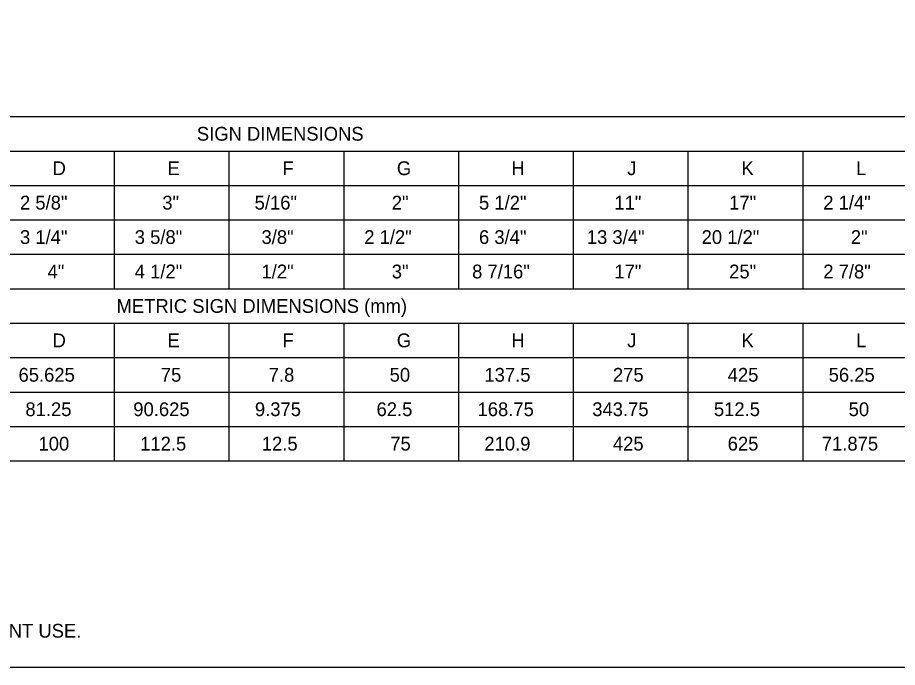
# Model space of a CAD drawing. Extents: x 49991.4 to 50021, y 49987.6 to 50011.4.
# Drawn here: x 50007.711 to 50011.545, y 49987.799 to 49990.63 of the extents above; entities that cross this region are included whole.
import ezdxf

# ---------------------------------------------------------------- set-up
doc = ezdxf.new("R2010")
doc.units = 0
doc.layers.add('Level 1', color=7, linetype='Continuous')
doc.layers.add('Level 2', color=7, linetype='Continuous')

msp = doc.modelspace()

# ---------------------------------------------------------------- linework, layer by layer
at = {"layer": 'Level 1'}
msp.add_lwpolyline([(49999.3835, 49998.9992), (50016.7501, 49998.9992), (50016.7501, 49987.7988), (49999.3835, 49987.7988)], close=True, dxfattribs=at)
at = {"layer": 'Level 2'}
for p, q in [((50005.0051, 49990.1985), (50013.6326, 49990.1985)), ((50006.1326, 49990.0485), (50013.6326, 49990.0485)), ((50008.1326, 49990.0485), (50008.1326, 49989.4485)), ((50008.6326, 49990.0485), (50008.6326, 49989.4485)), ((50009.1326, 49990.0485), (50009.1326, 49989.4485)), ((50009.6326, 49990.0485), (50009.6326, 49989.4485)), ((50010.1326, 49990.0485), (50010.1326, 49989.4485)), ((50010.6326, 49990.0485), (50010.6326, 49989.4485)), ((50011.1326, 49990.0485), (50011.1326, 49989.4485)), ((50005.0051, 49989.8985), (50013.6326, 49989.8985)), ((50005.0051, 49989.7485), (50013.6326, 49989.7485)), ((50005.0051, 49989.5985), (50013.6326, 49989.5985)), ((50005.0051, 49989.4485), (50013.6326, 49989.4485)), ((50005.0051, 49989.4485), (50013.6326, 49989.4485)), ((50006.1326, 49989.2985), (50013.6326, 49989.2985)), ((50008.1326, 49989.2985), (50008.1326, 49988.6985)), ((50008.6326, 49989.2985), (50008.6326, 49988.6985)), ((50009.1326, 49989.2985), (50009.1326, 49988.6985)), ((50009.6326, 49989.2985), (50009.6326, 49988.6985)), ((50010.1326, 49989.2985), (50010.1326, 49988.6985)), ((50010.6326, 49989.2985), (50010.6326, 49988.6985)), ((50011.1326, 49989.2985), (50011.1326, 49988.6985)), ((50005.0051, 49989.1485), (50013.6326, 49989.1485)), ((50005.0051, 49988.9985), (50013.6326, 49988.9985)), ((50005.0051, 49988.8485), (50013.6326, 49988.8485)), ((50005.0051, 49988.6985), (50013.6326, 49988.6985))]:
    msp.add_line(p, q, dxfattribs=at)

# ---------------------------------------------------------------- texts
for s, p in [('SIGN DIMENSIONS', (50008.4926, 49990.0935)), ('D', (50007.8639, 49989.9435)), ('E', (50008.3642, 49989.9435)), ('F', (50008.8654, 49989.9435)), ('G', (50009.3639, 49989.9435)), ('H', (50009.863, 49989.9435)), ('J', (50010.3677, 49989.9435)), ('K', (50010.8656, 49989.9435)), ('L', (50011.3656, 49989.9435)), ('2 5/8"', (50007.7219, 49989.7935)), ('3"', (50008.342, 49989.7935)), (' 5/16"', (50008.722, 49989.7935)), ('2"', (50009.342, 49989.7935)), ('5 1/2"', (50009.722, 49989.7935)), ('11"', (50010.3119, 49989.7935)), ('17"', (50010.812, 49989.7935)), ('2 1/4"', (50011.222, 49989.7935)), ('3 1/4"', (50007.7219, 49989.6435)), ('3 5/8"', (50008.222, 49989.6435)), (' 3/8"', (50008.752, 49989.6435)), ('2 1/2"', (50009.2219, 49989.6435)), ('6 3/4"', (50009.722, 49989.6435)), ('13 3/4"', (50010.1919, 49989.6435)), ('20 1/2"', (50010.692, 49989.6435)), ('2"', (50011.3421, 49989.6435)), ('4"', (50007.842, 49989.4935)), ('4 1/2"', (50008.222, 49989.4935)), (' 1/2"', (50008.752, 49989.4935)), ('3"', (50009.3419, 49989.4935)), ('8 7/16"', (50009.692, 49989.4935)), ('17"', (50010.3119, 49989.4935)), ('25"', (50010.812, 49989.4935)), ('2 7/8"', (50011.2221, 49989.4935)), ('METRIC SIGN DIMENSIONS (mm)', (50008.1426, 49989.3435)), ('D', (50007.8639, 49989.1935)), ('E', (50008.3642, 49989.1935)), ('F', (50008.8654, 49989.1935)), ('G', (50009.3639, 49989.1935)), ('H', (50009.863, 49989.1935)), ('J', (50010.3677, 49989.1935)), ('K', (50010.8656, 49989.1935)), ('L', (50011.3656, 49989.1935)), ('65.625', (50007.7155, 49989.0435)), ('75', (50008.3356, 49989.0435)), ('7.8', (50008.8056, 49989.0435)), ('50', (50009.3326, 49989.0435)), ('137.5', (50009.7456, 49989.0435)), ('275', (50010.3055, 49989.0435)), ('425', (50010.8056, 49989.0435)), ('56.25', (50011.2456, 49989.0435)), ('81.25', (50007.7455, 49988.8935)), ('90.625', (50008.2156, 49988.8935)), ('9.375', (50008.7456, 49988.8935)), ('62.5', (50009.2755, 49988.8935)), ('168.75', (50009.7156, 49988.8935)), ('343.75', (50010.2155, 49988.8935)), ('512.5', (50010.7456, 49988.8935)), ('50', (50011.3327, 49988.8935)), ('100', (50007.8026, 49988.7435)), ('112.5', (50008.2456, 49988.7435)), ('12.5', (50008.7756, 49988.7435)), ('75', (50009.3355, 49988.7435)), ('210.9', (50009.7454, 49988.7435)), ('425', (50010.3055, 49988.7435)), ('625', (50010.8056, 49988.7435)), ('71.875', (50011.2157, 49988.7435)), ('*** USE WITH STANDARD 42" [1050] U.S. SHIELD AND ALL INDEPENDENT USE.', (50004.978, 49987.9284))]:
    msp.add_text(s, height=0.06, dxfattribs=at).set_placement(p)

doc.saveas('drawing.dxf')
